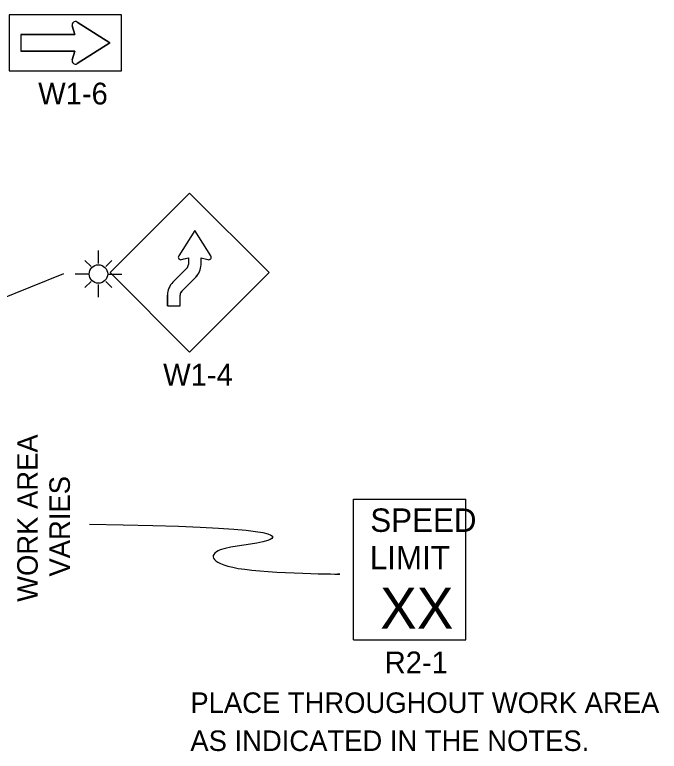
# Model space of a CAD drawing. Extents: x 16038 to 19504, y 5710 to 8321.
# Drawn here: x 17203.6 to 17423.7, y 6352.6 to 6604.1 of the extents above; entities that cross this region are included whole.
import ezdxf

# ---------------------------------------------------------------- set-up
doc = ezdxf.new("R2010")
doc.units = 0
doc.layers.add('TRAFFIC_SIGNS_PR', color=7, linetype='Continuous')
doc.layers.add('TYPICAL_TEXT_DIMEN_PR', color=7, linetype='Continuous')

msp = doc.modelspace()

# ---------------------------------------------------------------- linework, layer by layer
at = {"layer": 'TRAFFIC_SIGNS_PR'}
for p, q in [((17224.89, 6601.65), (17236.05, 6594.55)), ((17224.05, 6597.35), (17223.21, 6600.41)), ((17205.65, 6597.35), (17224.05, 6597.35)), ((17205.65, 6597.35), (17205.65, 6591.75)), ((17236.05, 6594.55), (17224.89, 6587.45)), ((17224.05, 6591.75), (17205.65, 6591.75)), ((17223.21, 6588.69), (17224.05, 6591.75)), ((17263.28, 6543.23), (17236.12, 6516.08)), ((17290.43, 6516.08), (17263.28, 6543.23)), ((17232.17, 6519.16), (17232.17, 6523.66)), ((17229.65, 6518.12), (17227.55, 6520.22)), ((17234.68, 6518.12), (17236.79, 6520.22)), ((17229.01, 6515.6), (17224.18, 6515.6)), ((17235.32, 6515.6), (17240.2, 6515.6)), ((17236.12, 6516.08), (17263.28, 6488.92)), ((17257.62, 6512.83), (17262.34, 6517.54)), ((17262.34, 6517.54), (17257.62, 6512.83)), ((17263.28, 6488.92), (17290.43, 6516.08)), ((17229.65, 6513.09), (17227.55, 6510.98)), ((17234.68, 6513.09), (17236.79, 6510.98)), ((17260.67, 6509.77), (17265.39, 6514.49)), ((17260.67, 6509.77), (17265.39, 6514.49)), ((17232.17, 6507.64), (17232.17, 6512.05)), ((17255.75, 6504.71), (17255.75, 6508.4)), ((17260.07, 6504.71), (17260.07, 6508.4)), ((17255.75, 6504.71), (17260.07, 6504.71)), ((17319.28, 6438.67), (17357.68, 6438.67)), ((17319.28, 6390.67), (17319.28, 6438.67)), ((17357.68, 6390.67), (17357.68, 6438.67)), ((17319.28, 6390.67), (17357.68, 6390.67))]:
    msp.add_line(p, q, dxfattribs=at)
msp.add_lwpolyline([(17201.65, 6584.95), (17240.05, 6584.95), (17240.05, 6604.15), (17201.65, 6604.15)], close=True, dxfattribs=at)
for points in [[(17224.89, 6587.45), (17236.05, 6594.55), (17224.89, 6601.65)], [(17223.21, 6600.41), (17224.05, 6597.35), (17205.65, 6597.35), (17205.65, 6591.75), (17224.05, 6591.75), (17223.21, 6588.69)], [(17270.54, 6521.81), (17265.06, 6530.42), (17259.58, 6521.81)], [(17270.54, 6521.81), (17265.06, 6530.42), (17259.58, 6521.81)], [(17260.54, 6520.52), (17262.9, 6521.16), (17262.9, 6518.87)], [(17260.54, 6520.51), (17261.37, 6520.74), (17262.9, 6521.16), (17262.9, 6518.87)], [(17267.21, 6518.8), (17267.22, 6521.16), (17269.58, 6520.52)], [(17255.75, 6508.4), (17255.75, 6504.71), (17260.07, 6504.71), (17260.07, 6508.4)]]:
    msp.add_lwpolyline(points, dxfattribs=at)
msp.add_circle((17232.17, 6515.6), 3.15, dxfattribs=at)
for centre, radius, start, end in [((17224.29, 6600.71), 1.12, 57.5304, 195.3269), ((17224.29, 6600.71), 1.12, 57.5304, 195.3269), ((17224.29, 6588.39), 1.12, 164.6731, 302.4696), ((17224.29, 6588.39), 1.12, 164.6731, 302.4696), ((17260.31, 6521.35), 0.864, 147.5204, 285.3986), ((17260.31, 6521.35), 0.866, 147.5288, 285.3852), ((17269.81, 6521.35), 0.866, 254.6799, 32.2804), ((17261.05, 6518.87), 1.85, 314.2125, 0), ((17261.04, 6518.87), 1.85, 314.2123, 0.1238), ((17261.05, 6518.87), 6.17, 314.2125, 359.3819), ((17261.04, 6518.87), 6.17, 314.7687, 359.3755), ((17261.92, 6508.41), 6.17, 134.2125, 180), ((17261.92, 6508.41), 6.17, 134.2125, 180), ((17261.92, 6508.4), 6.17, 134.2117, 180), ((17261.92, 6508.4), 1.85, 132.372, 180), ((17261.92, 6508.41), 1.85, 134.2125, 180)]:
    msp.add_arc(centre, radius, start, end, dxfattribs=at)
at = {"layer": 'TYPICAL_TEXT_DIMEN_PR'}
msp.add_line((17220.27, 6515.7), (17186.28, 6502.03), dxfattribs=at)
msp.add_open_spline([(17229.09, 6430.12), (17294.83, 6429.41), (17293.87, 6423.01), (17269.72, 6423.01), (17269.72, 6413.1), (17319.37, 6413.1), (17313.84, 6413.1)], degree=3, dxfattribs=at)

# ---------------------------------------------------------------- texts
at = {"layer": 'TRAFFIC_SIGNS_PR'}
for s, height, p in [('W1-6', 7.44, (17211.59, 6573.51)), ('W1-4', 7.44, (17254.28, 6477.49)), ('SPEED', 8, (17325.04, 6427.53)), ('LIMIT', 8, (17324.88, 6414.73)), ('XX', 14.031, (17328.39, 6394.43)), ('R2-1', 7.44, (17329.95, 6379.23)), ('PLACE THROUGHOUT WORK AREA', 7, (17263.57, 6365.7)), ('AS INDICATED IN THE NOTES.', 7, (17263.57, 6352.7))]:
    msp.add_text(s, height=height, dxfattribs=at).set_placement(p)
at = {"layer": 'TYPICAL_TEXT_DIMEN_PR'}
for s, p in [('WORK AREA', (17211.42, 6403.63)), ('VARIES', (17222.42, 6412.27))]:
    msp.add_text(s, height=7, rotation=90, dxfattribs=at).set_placement(p)

doc.saveas('drawing.dxf')
